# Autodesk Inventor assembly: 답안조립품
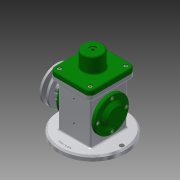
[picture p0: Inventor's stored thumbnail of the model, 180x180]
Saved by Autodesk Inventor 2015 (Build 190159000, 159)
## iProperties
Created: 2019-08
Part Number: 답안조립품
Document SubType Name: Assembly
Designer: now
Author: now
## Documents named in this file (18)
- C:\Users\now\Desktop\490804V1034\답안조립품.iam
- C:\Users\now\Desktop\490804V1034\E-링.ipt
- C:\Users\now\Desktop\490804V1034\V-벨트풀리.ipt
- C:\Users\now\Desktop\490804V1034\덮개.ipt
- C:\Users\now\Desktop\490804V1034\뒤커버.ipt
- C:\Users\now\Desktop\490804V1034\링크.ipt
- C:\Users\now\Desktop\490804V1034\베어링 17 x 40 x 12.ipt
- C:\Users\now\Desktop\490804V1034\본체.ipt
- C:\Users\now\Desktop\490804V1034\볼트 M4 x 8.ipt
- C:\Users\now\Desktop\490804V1034\볼트 M4 x 10.ipt
- C:\Users\now\Desktop\490804V1034\슬라이더.ipt
- C:\Users\now\Desktop\490804V1034\앞커버.ipt
- C:\Users\now\Desktop\490804V1034\오일 실 17 30 8.ipt
- C:\Users\now\Desktop\490804V1034\와셔 4x16.ipt
- C:\Users\now\Desktop\490804V1034\클레비스 핀 6 x 22.ipt
- 클레비스 핀 6 x 22.ipt
- C:\Users\now\Desktop\490804V1034\키 4 x 4 x 12.ipt
- C:\Users\now\Desktop\490804V1034\편심축.ipt
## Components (2 placed, 2 different names)
1. E-링:1
2. V-벨트풀리:1 — 각도:2
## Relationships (1: Angle 1)
- 각도:2 [Angle]: V-벨트풀리:1
